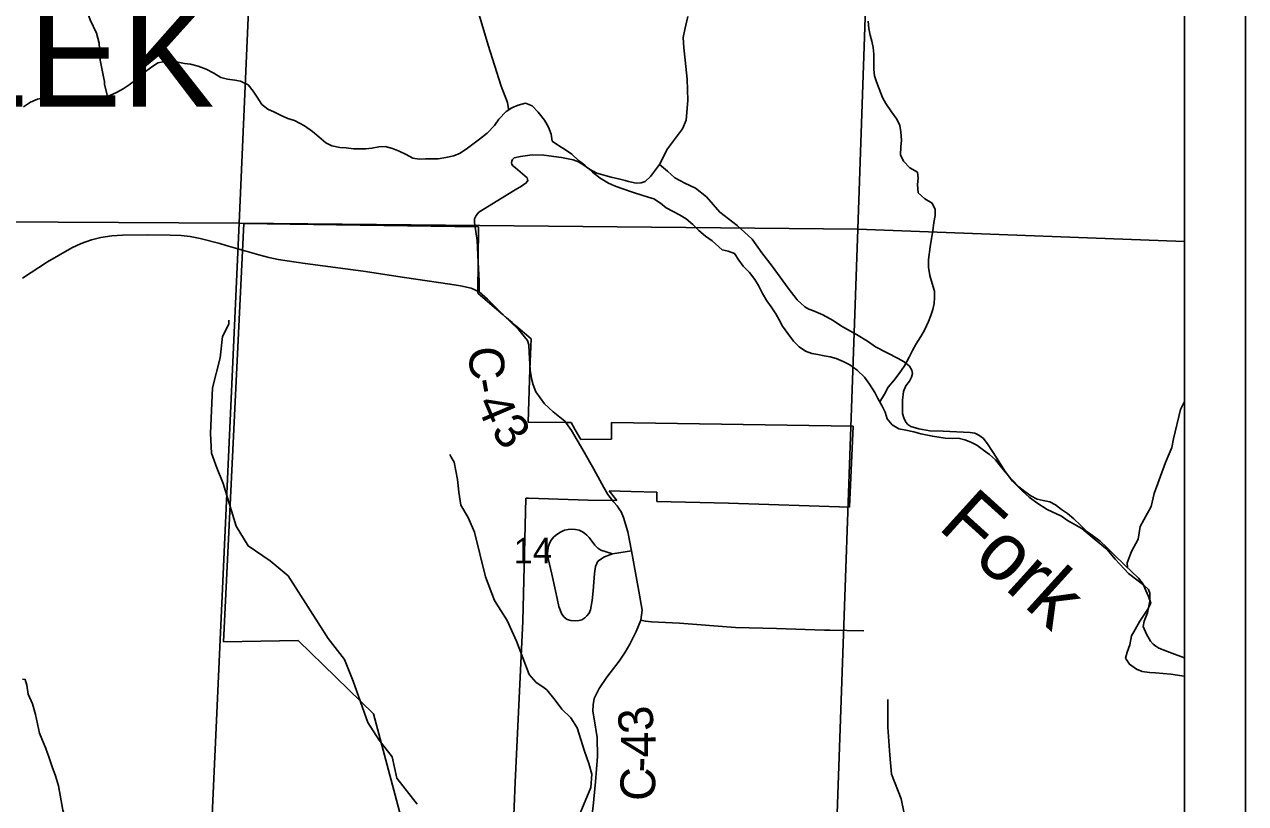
# Model space of a CAD drawing. Extents: x -19 to 40.8, y -1.8 to 26.1.
# Drawn here: x 7.005 to 9, y 17.001 to 18.273 of the extents above; entities that cross this region are included whole.
import ezdxf

# ---------------------------------------------------------------- set-up
doc = ezdxf.new("R2010")
doc.units = 0
for name, color, linetype in [('Default', 7, 'Continuous'), ('GM_X_Corporation', 7, 'Continuous'), ('GM_X_County_Road_Text', 7, 'Continuous'), ('GM_X_Minor_River', 7, 'Continuous'), ('GM_X_Section', 7, 'Continuous'), ('GM_X_Section_Text', 7, 'Continuous'), ('GM_X_State_Route', 7, 'Continuous'), ('GM_X_Township_Text', 7, 'Continuous'), ('RW_P_Text', 7, 'Continuous'), ('SH_Data', 7, 'Continuous')]:
    doc.layers.add(name, color=color, linetype=linetype)

msp = doc.modelspace()

# ---------------------------------------------------------------- linework, layer by layer
at = {"layer": 'Default'}
for p, q in [((7.3634, 17.9485), (7.3301, 17.2649)), ((7.5147, 17.9463), (7.3634, 17.9485)), ((7.747, 17.9429), (7.5147, 17.9463)), ((7.7455, 17.8346), (7.747, 17.9429)), ((7.769, 17.8144), (7.7455, 17.8346)), ((7.7869, 17.799), (7.769, 17.8144)), ((7.7926, 17.7942), (7.7869, 17.799)), ((7.8017, 17.7864), (7.7926, 17.7942)), ((7.8074, 17.7815), (7.8017, 17.7864)), ((7.8328, 17.7598), (7.8074, 17.7815)), ((7.8308, 17.71), (7.8328, 17.7598)), ((7.8277, 17.6238), (7.8308, 17.71)), ((7.8887, 17.623), (7.8277, 17.6238)), ((7.898, 17.623), (7.8887, 17.623)), ((7.9047, 17.6111), (7.898, 17.623)), ((8.3588, 17.6174), (7.964, 17.6229)), ((7.964, 17.6229), (7.964, 17.5957)), ((8.3531, 17.4848), (8.3588, 17.6174)), ((7.9138, 17.5956), (7.9047, 17.6111)), ((7.964, 17.5957), (7.9138, 17.5956)), ((7.8191, 17.2985), (7.824, 17.4997)), ((7.824, 17.4997), (7.8283, 17.4995)), ((7.8283, 17.4995), (7.9094, 17.4967)), ((7.9728, 17.4955), (7.9603, 17.5114)), ((7.9603, 17.5114), (7.9962, 17.5102)), ((7.9962, 17.5102), (8.038, 17.5093)), ((8.038, 17.5093), (8.0382, 17.4942)), ((7.9094, 17.4967), (7.9261, 17.4964)), ((7.9261, 17.4964), (7.9728, 17.4955)), ((8.0382, 17.4942), (8.1551, 17.4911)), ((8.1551, 17.4911), (8.3531, 17.4848)), ((7.8065, 17.0357), (7.8191, 17.2985)), ((7.3301, 17.2649), (7.4519, 17.2669)), ((7.4519, 17.2669), (7.5751, 17.147)), ((7.5751, 17.147), (7.6369, 16.9157)), ((7.8016, 16.917), (7.8065, 17.0357))]:
    msp.add_line(p, q, dxfattribs=at)
for points in [[(8.9, 17.9188), (8.9, 18.9056), (8.4001, 18.9137), (8.3666, 17.9389)], [(8.9, 16.8989), (8.9, 17.9188), (8.3666, 17.9389), (8.3301, 16.9076)]]:
    msp.add_lwpolyline(points, close=True, dxfattribs=at)
at = {"layer": 'GM_X_Corporation'}
for points in [[(7.002, 17.8591), (7.0427, 17.8858), (7.0822, 17.9084), (7.0975, 17.9157), (7.1143, 17.9214), (7.1299, 17.9253), (7.1478, 17.9279), (7.1654, 17.9292), (7.2059, 17.9297), (7.243, 17.9292), (7.2608, 17.9285), (7.2756, 17.9271), (7.292, 17.924), (7.324, 17.9155), (7.3347, 17.9125)], [(7.3347, 17.9125), (7.3879, 17.8973), (7.4042, 17.8929), (7.4196, 17.8896), (7.4637, 17.883), (7.5583, 17.8703), (7.626, 17.86), (7.7, 17.8494), (7.7171, 17.8465), (7.7347, 17.8425), (7.748, 17.8364)], [(7.748, 17.8364), (7.7615, 17.8248), (7.7845, 17.8015), (7.8122, 17.7749), (7.8221, 17.7632), (7.8267, 17.7569), (7.8288, 17.7499)], [(7.8288, 17.7499), (7.8291, 17.7489), (7.8299, 17.7276), (7.8312, 17.7087), (7.8331, 17.6952), (7.8359, 17.6847), (7.8404, 17.673), (7.8544, 17.6538), (7.8686, 17.6407), (7.8824, 17.6298)], [(7.8824, 17.6298), (7.888, 17.6254), (7.8986, 17.6101), (7.9172, 17.5784), (7.9352, 17.5468), (7.9513, 17.517), (7.9579, 17.5055), (7.9597, 17.5033)], [(7.9597, 17.5033), (7.9681, 17.4928), (7.9735, 17.4869), (7.9763, 17.4828), (7.9796, 17.4771), (7.9835, 17.468), (7.9906, 17.4445), (7.9966, 17.4133)], [(7.9966, 17.4133), (8.0089, 17.3477), (8.0139, 17.3164), (8.0122, 17.3002), (8.0046, 17.2819), (7.9939, 17.261), (7.9865, 17.2479), (7.9767, 17.2334), (7.9567, 17.2069), (7.944, 17.1887), (7.9394, 17.1801), (7.936, 17.172), (7.9339, 17.1618), (7.9338, 17.1515), (7.9356, 17.1389), (7.9405, 17.1086), (7.9411, 17.0777), (7.9379, 17.0363), (7.9343, 16.9966), (7.9326, 16.9836)]]:
    msp.add_lwpolyline(points, dxfattribs=at)
at = {"layer": 'GM_X_Section'}
for points in [[(7.1409, 18.1563), (7.1357, 18.1752), (7.1356, 18.1801), (7.1347, 18.185), (7.1286, 18.215), (7.1269, 18.2431), (7.1225, 18.2593), (7.1123, 18.2812), (7.0988, 18.3183), (7.0877, 18.3439), (7.0715, 18.3657), (7.0568, 18.3826), (7.0402, 18.4021), (7.0239, 18.4231), (7.0033, 18.4573), (6.9789, 18.4881), (6.9335, 18.5155), (6.8768, 18.5366), (6.8073, 18.5541), (6.7892, 18.5694), (6.7304, 18.6079), (6.7022, 18.6204), (6.6987, 18.623)], [(7.7956, 18.1334), (7.7956, 18.1354), (7.7943, 18.1457), (7.784, 18.1725), (7.7628, 18.2398), (7.748, 18.289)], [(8.4025, 17.6569), (8.4099, 17.6695), (8.416, 17.6807), (8.4251, 17.692), (8.4339, 17.7033), (8.4426, 17.7157), (8.4502, 17.73), (8.4559, 17.7409), (8.462, 17.7517), (8.4696, 17.7637), (8.4754, 17.7742), (8.4818, 17.7881), (8.486, 17.7981), (8.4888, 17.8077), (8.4911, 17.8176), (8.492, 17.8276), (8.4916, 17.8378), (8.4882, 17.8503), (8.4844, 17.8634), (8.4821, 17.8767), (8.4817, 17.8896), (8.4848, 17.9099), (8.487, 17.924), (8.4889, 17.9362), (8.4908, 17.9496), (8.4927, 17.9611), (8.4928, 17.971), (8.4879, 17.9815), (8.4759, 17.9887), (8.4653, 17.9982), (8.4641, 18.0119), (8.465, 18.0222), (8.4639, 18.032), (8.4515, 18.0393), (8.4413, 18.05), (8.436, 18.0605), (8.4367, 18.0738), (8.4376, 18.0837), (8.4367, 18.0978), (8.4349, 18.1084), (8.43, 18.1189), (8.4216, 18.1308), (8.4121, 18.1442), (8.4069, 18.1539), (8.4011, 18.1682), (8.3969, 18.1794), (8.394, 18.1896), (8.3925, 18.1998), (8.3929, 18.2124), (8.3929, 18.2246), (8.3917, 18.236), (8.3895, 18.2462), (8.3869, 18.256), (8.3847, 18.2669), (8.3832, 18.2787)], [(8.1065, 17.9369), (8.0967, 17.9465), (8.0861, 17.9557), (8.0749, 17.9622), (8.0648, 17.968), (8.0536, 17.9737), (8.0439, 17.9814), (8.0334, 17.9887), (8.0238, 17.991), (8.0134, 17.9945), (8.0019, 17.9983), (7.9792, 18.006), (7.9688, 18.0099), (7.9592, 18.0141), (7.9457, 18.0221), (7.9328, 18.0319), (7.9203, 18.0434), (7.9101, 18.0514), (7.8992, 18.0613), (7.8887, 18.0686), (7.8774, 18.0759), (7.8673, 18.0828), (7.8655, 18.0941), (7.8613, 18.1058), (7.8545, 18.117), (7.8442, 18.13), (7.8347, 18.1407), (7.8236, 18.1446), (7.8115, 18.1415), (7.8014, 18.137), (7.7917, 18.131), (7.7799, 18.1185), (7.773, 18.1084), (7.7609, 18.0958), (7.7482, 18.0859), (7.7286, 18.0713), (7.717, 18.0633), (7.7065, 18.0588), (7.6933, 18.0561), (7.6808, 18.0538), (7.6603, 18.0539), (7.6497, 18.0536), (7.6393, 18.0552), (7.6285, 18.0609), (7.6169, 18.0663), (7.6065, 18.0709), (7.5943, 18.0743), (7.584, 18.0736), (7.5727, 18.0713), (7.5628, 18.0703), (7.553, 18.07), (7.5423, 18.0704), (7.5305, 18.0716), (7.5202, 18.0724), (7.5072, 18.075), (7.4971, 18.08), (7.4858, 18.0899), (7.4756, 18.0988), (7.4624, 18.1078), (7.4462, 18.1165), (7.4351, 18.1199), (7.4246, 18.1245), (7.4135, 18.1299), (7.4027, 18.1349), (7.3929, 18.1429), (7.3853, 18.1545), (7.3785, 18.1646), (7.3702, 18.175), (7.3582, 18.181), (7.3487, 18.1826), (7.3369, 18.1842), (7.3257, 18.1869), (7.3145, 18.1937), (7.3018, 18.2002), (7.2887, 18.2055), (7.276, 18.2085), (7.2665, 18.2097), (7.2558, 18.2117), (7.2451, 18.2133), (7.2344, 18.2129), (7.2231, 18.2107), (7.2108, 18.2027), (7.2004, 18.1947), (7.1875, 18.1837), (7.176, 18.1746), (7.1663, 18.1682), (7.1551, 18.1621), (7.1442, 18.1572), (7.1321, 18.1538), (7.1219, 18.1516), (7.1082, 18.1512), (7.0938, 18.1515), (7.0793, 18.1529), (7.0667, 18.1541), (7.0568, 18.1545), (7.0473, 18.1542), (7.0375, 18.1535), (7.0261, 18.1513), (7.0149, 18.1463), (7.0033, 18.1388)], [(8.9, 17.2088), (8.8991, 17.209), (8.8888, 17.2106), (8.8781, 17.2118), (8.853, 17.214), (8.8431, 17.2148), (8.8312, 17.2164), (8.8216, 17.2203), (8.8103, 17.2283), (8.8039, 17.238), (8.8063, 17.2479), (8.8109, 17.2598), (8.8138, 17.2744), (8.8196, 17.2852), (8.8271, 17.2984), (8.8337, 17.3085), (8.8402, 17.3182), (8.8452, 17.3282), (8.8414, 17.3387), (8.837, 17.3485), (8.8325, 17.359), (8.8253, 17.369), (8.8136, 17.3797), (8.8034, 17.3897), (8.7838, 17.4084), (8.7732, 17.4188), (8.7622, 17.4291), (8.7501, 17.4386), (8.7404, 17.4451), (8.731, 17.4547), (8.7196, 17.4658), (8.7091, 17.4746), (8.6994, 17.4811), (8.6896, 17.4884), (8.68, 17.4934), (8.6692, 17.4958), (8.6593, 17.4981), (8.6492, 17.5031), (8.6391, 17.5104), (8.6294, 17.5181), (8.6188, 17.5295), (8.6089, 17.5406), (8.5998, 17.5518), (8.5915, 17.5622), (8.5814, 17.571), (8.5716, 17.5779), (8.5607, 17.5859), (8.5511, 17.5909), (8.5411, 17.5948), (8.5307, 17.5975), (8.5212, 17.5972), (8.5094, 17.5973), (8.4987, 17.5992), (8.4884, 17.6008), (8.4697, 17.6044), (8.4582, 17.6078), (8.4448, 17.6108), (8.4333, 17.6128), (8.4228, 17.6193), (8.4145, 17.6293), (8.4112, 17.6398), (8.4059, 17.6511), (8.3994, 17.6623), (8.3942, 17.6724), (8.3858, 17.6858), (8.3774, 17.697), (8.3653, 17.7088), (8.3536, 17.7172), (8.3428, 17.7229), (8.3312, 17.7275), (8.3213, 17.7306), (8.3117, 17.7318), (8.3014, 17.7342), (8.2911, 17.7361), (8.2811, 17.7396), (8.2709, 17.7469), (8.2612, 17.7561), (8.252, 17.7688), (8.2437, 17.7807), (8.238, 17.7908), (8.2324, 17.8005), (8.2248, 17.812), (8.2177, 17.8217), (8.2108, 17.8337), (8.2043, 17.8468), (8.1983, 17.8569), (8.1896, 17.868), (8.1794, 17.8783), (8.1719, 17.8884), (8.1651, 17.8992), (8.1547, 17.903), (8.1451, 17.9054), (8.1287, 17.9197), (8.1174, 17.9278), (8.1065, 17.9369)], [(7.6465, 16.9996), (7.6132, 17.0423), (7.6058, 17.0772), (7.5845, 17.1042), (7.5662, 17.1328), (7.542, 17.2004), (7.5277, 17.2359), (7.501, 17.2705), (7.4357, 17.3728), (7.4065, 17.3974), (7.3702, 17.4215), (7.3511, 17.4539), (7.3298, 17.5234), (7.3195, 17.5491), (7.3104, 17.5729), (7.3091, 17.6052), (7.3123, 17.6797), (7.3247, 17.7286), (7.3286, 17.7636), (7.3388, 17.7839), (7.3387, 17.7904)], [(8.8071, 17.386), (8.8063, 17.3939), (8.8136, 17.4126), (8.8246, 17.4326), (8.828, 17.4531), (8.8459, 17.4857), (8.8508, 17.5071), (8.8692, 17.558), (8.8797, 17.5821), (8.8825, 17.5962), (8.8937, 17.6443), (8.9, 17.6576)], [(7.9129, 16.9852), (7.9303, 17.0266), (7.9318, 17.0486), (7.9273, 17.066), (7.9201, 17.0861), (7.9077, 17.1246), (7.8976, 17.1408), (7.883, 17.1546), (7.8718, 17.1697), (7.8582, 17.1862), (7.8517, 17.1914), (7.841, 17.1984), (7.8298, 17.2116), (7.8088, 17.2659), (7.7935, 17.2999), (7.7729, 17.3326), (7.7582, 17.3708), (7.7403, 17.4439), (7.73, 17.468), (7.7179, 17.488), (7.7145, 17.5092), (7.7123, 17.5301), (7.7069, 17.5581), (7.7022, 17.5664), (7.7002, 17.5709)], [(7.1594, 16.7991), (7.1616, 16.8229), (7.1588, 16.8312), (7.1521, 16.849), (7.1307, 16.8634), (7.1163, 16.8822), (7.097, 16.929), (7.086, 16.9501), (7.0743, 16.9693), (7.0679, 16.9901), (7.0604, 17.0295), (7.0556, 17.0458), (7.05, 17.0605), (7.0456, 17.0756), (7.0397, 17.0907), (7.0298, 17.1156), (7.0228, 17.1459), (7.018, 17.1637), (7.0112, 17.1792), (7.0087, 17.1943), (7.0059, 17.2034), (7.0017, 17.2041)], [(8.4457, 16.9688), (8.4371, 17.0081), (8.4213, 17.0486), (8.4188, 17.0797), (8.4154, 17.1256), (8.4156, 17.1541), (8.4153, 17.1708)]]:
    msp.add_lwpolyline(points, dxfattribs=at)
at = {"layer": 'GM_X_State_Route'}
msp.add_line((8.3206, 17.2838), (8.3764, 17.283), dxfattribs=at)
for points in [[(6.9993, 15.9207), (7.1288, 15.9169), (7.6101, 15.9059), (8.0135, 15.8966), (8.0191, 15.8965), (8.0312, 15.8982), (8.1843, 15.8933), (8.1919, 15.8932), (8.7332, 15.8828), (8.7397, 15.8827), (8.8013, 15.8813), (8.8296, 15.8807), (8.9, 15.8791), (8.9, 20.9)], [(7.9862, 18.0184), (7.9919, 18.0167), (8.0046, 18.0139), (8.0126, 18.0146), (8.019, 18.0169), (8.0277, 18.0251), (8.0424, 18.0445), (8.0557, 18.0704), (8.0802, 18.1029), (8.0858, 18.1172), (8.0887, 18.1491), (8.0876, 18.1839), (8.0843, 18.2153), (8.0822, 18.235), (8.0809, 18.2519), (8.0839, 18.2651), (8.0887, 18.2864)], [(7.7407, 17.9461), (7.7401, 17.9501), (7.7402, 17.9559), (7.7429, 17.9614), (7.7474, 17.967), (7.8068, 18.0032), (7.8169, 18.0092), (7.8248, 18.0145), (7.8271, 18.0187), (7.8265, 18.0227), (7.8189, 18.0294), (7.8074, 18.039), (7.8029, 18.0425), (7.801, 18.0453), (7.8005, 18.0476), (7.801, 18.0503), (7.8023, 18.053), (7.8051, 18.0555), (7.8156, 18.0578), (7.8347, 18.0605), (7.8533, 18.0596), (7.8823, 18.0559), (7.9017, 18.0522), (7.9103, 18.0491), (7.9156, 18.0459), (7.9283, 18.0372), (7.9403, 18.0306), (7.9633, 18.0242), (7.9777, 18.0209), (7.9862, 18.0184)], [(8.9, 17.2389), (8.8943, 17.2409), (8.8795, 17.2464), (8.8585, 17.2547), (8.8535, 17.2577), (8.8491, 17.2609), (8.8447, 17.2657), (8.8382, 17.2774), (8.8327, 17.2901), (8.8344, 17.2986), (8.8397, 17.3124), (8.8436, 17.331), (8.8438, 17.3381), (8.8437, 17.3443), (8.8413, 17.3502), (8.8339, 17.3575), (8.8086, 17.3762), (8.787, 17.4001), (8.7741, 17.4155), (8.7529, 17.433), (8.7324, 17.4498), (8.7092, 17.4631), (8.6994, 17.4702), (8.6756, 17.4808), (8.6587, 17.4918), (8.6465, 17.5012), (8.6355, 17.511), (8.619, 17.5271), (8.6072, 17.5431), (8.5924, 17.5664), (8.5797, 17.5865), (8.5718, 17.5969), (8.5643, 17.6023), (8.5579, 17.6056), (8.5502, 17.6067), (8.5062, 17.6091), (8.4844, 17.6098), (8.466, 17.613), (8.453, 17.6166), (8.4483, 17.6201), (8.4451, 17.6237), (8.4415, 17.6307), (8.4393, 17.6381), (8.4396, 17.6596), (8.441, 17.6736), (8.4452, 17.683), (8.451, 17.6909), (8.4543, 17.6973), (8.4558, 17.7034), (8.455, 17.7085), (8.4508, 17.715), (8.4424, 17.7221), (8.4324, 17.7276), (8.3953, 17.7467), (8.3824, 17.7561), (8.3642, 17.7669), (8.3401, 17.7804), (8.3261, 17.79), (8.3094, 17.799), (8.2939, 17.8053), (8.2863, 17.8085), (8.2799, 17.8121), (8.2672, 17.8234), (8.2526, 17.8426), (8.2267, 17.8787), (8.2094, 17.9003), (8.194, 17.9229), (8.1693, 17.9452), (8.1413, 17.9666), (8.1195, 17.9916), (8.1012, 18.0059), (8.084, 18.0141), (8.0677, 18.0229), (8.0553, 18.0339), (8.0424, 18.0445)], [(7.748, 17.8364), (7.748, 17.8543), (7.7464, 17.8848), (7.7445, 17.9204), (7.7407, 17.9461)], [(7.9659, 17.4085), (7.9466, 17.4145), (7.9417, 17.4179), (7.9369, 17.4225), (7.9277, 17.4352), (7.9239, 17.4392), (7.9202, 17.4421), (7.9158, 17.445), (7.9113, 17.4471), (7.905, 17.4484), (7.8991, 17.4489), (7.8934, 17.4486), (7.8872, 17.447), (7.8806, 17.444), (7.8745, 17.4401), (7.8697, 17.4361), (7.8655, 17.431), (7.8628, 17.4261), (7.861, 17.4213), (7.8598, 17.4153), (7.8597, 17.4088), (7.8608, 17.4012), (7.8665, 17.3752), (7.8735, 17.3432), (7.8781, 17.3223), (7.883, 17.3098), (7.8865, 17.3053), (7.8914, 17.3014), (7.8975, 17.2997), (7.9049, 17.299), (7.911, 17.2995), (7.9158, 17.301), (7.9203, 17.3038), (7.924, 17.3074), (7.9276, 17.3118), (7.9299, 17.3171), (7.9325, 17.3322), (7.9343, 17.3483), (7.9361, 17.3764), (7.9377, 17.3879), (7.9419, 17.3964), (7.9526, 17.4038), (7.9659, 17.4085), (7.9966, 17.4133)], [(8.0122, 17.3002), (8.0194, 17.2985), (8.0295, 17.2976), (8.0752, 17.2952), (8.1666, 17.2884), (8.2337, 17.2866), (8.3122, 17.2839), (8.3206, 17.2838)]]:
    msp.add_lwpolyline(points, dxfattribs=at)
at = {"layer": 'RW_P_Text'}
for points in [[(6.4041, 18.9461), (7.3987, 18.9308), (7.3559, 17.9489), (6.3691, 17.9545)], [(7.3987, 18.9308), (8.4001, 18.9137), (8.3666, 17.9389), (7.3559, 17.9489)], [(6.3691, 17.9545), (7.3559, 17.9489), (7.309, 16.9219), (6.3345, 16.9403)], [(7.3559, 17.9489), (8.3666, 17.9389), (8.3301, 16.9076), (7.309, 16.9219)]]:
    msp.add_lwpolyline(points, close=True, dxfattribs=at)
at = {"layer": 'SH_Data'}
for p, q in [((9, 21), (9, 14)), ((8.9, 20.9), (8.9, 14.1))]:
    msp.add_line(p, q, dxfattribs=at)

# ---------------------------------------------------------------- texts
at = {"layer": 'GM_X_County_Road_Text'}
for s, rotation, p in [('C', 272.7018, (7.7308, 17.7462)), ('-', 280.1308, (7.7339, 17.6916)), ('4', 293.1205, (7.742, 17.6552)), ('3', 310.1476, (7.7654, 17.6074)), ('3', 100.119, (8.0353, 17.1217)), ('4', 90.1632, (8.0364, 17.0759)), ('-', 88.9286, (8.0359, 17.0513)), ('C', 88.6221, (8.0348, 17.0043))]:
    msp.add_text(s, height=0.0568, rotation=rotation, dxfattribs=at).set_placement(p)
at = {"layer": 'GM_X_Minor_River'}
msp.add_text('Fork', height=0.09471, rotation=317.8356, dxfattribs=at).set_placement((8.4955, 17.4509))
at = {"layer": 'GM_X_Section_Text'}
msp.add_text('14', height=0.04186, rotation=0, dxfattribs=at).set_placement((7.8044, 17.3929))
at = {"layer": 'GM_X_Township_Text'}
msp.add_text('CREEK', height=0.17045, rotation=0, dxfattribs=at).set_placement((6.5302, 18.139))

doc.saveas('drawing.dxf')
